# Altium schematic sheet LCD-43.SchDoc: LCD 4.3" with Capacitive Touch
size A4; Date: 25-FEB-2015; Author: A.B; CompanyName: STMicroelectronics; Address1: 12, Rue Jules HOROWITZ; Address2: 38019 Grenoble; Address3: FRANCE; DocumentNumber: MB1191; Revision: B-02; SheetNumber: 14; SheetTotal: 14; Project: STM32F746G-DISCO
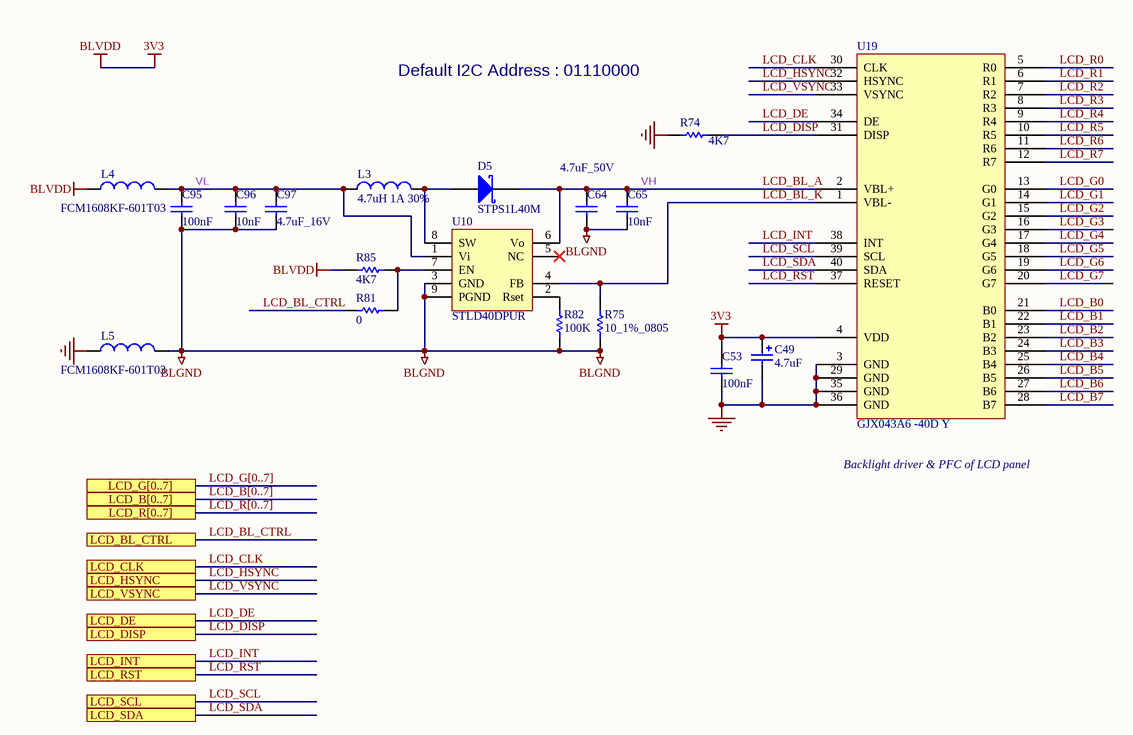
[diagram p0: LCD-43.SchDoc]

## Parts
C49  4.7uF  [TAN-A]
C53  100nF  [0402C]
C64  4.7uF_50V  [1206C]
C65  10nF  [0603C]
C95  100nF  [0603C]
C96  10nF  [0603C]
C97  4.7uF_16V  [1206C]
D5  STPS1L40M  [DO216-AA]
L3  4.7uH 1A 30%  [1210L]
L4  FCM1608KF-601T03  [0603L]
L5  FCM1608KF-601T03  [0603L]
R74  4K7  [0402R]
R75  10_1%_0805  [0805R]
R81  0  [0402R]
R82  100K  [0402R]
R85  4K7  [0402R]
U10  STLD40DPUR  [QFN8_0R65_3X3_ST]
U19  GJX043A6 -40D Y  [LCD_Kunjian_ HT043C_40P_P080_FLEX_FOLDED]

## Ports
LCD_B[0..7], LCD_BL_CTRL, LCD_CLK, LCD_DE, LCD_DISP, LCD_G[0..7], LCD_HSYNC, LCD_INT, LCD_R[0..7], LCD_RST, LCD_SCL, LCD_SDA, LCD_VSYNC

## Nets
3V3: C49.1 C53.2 L4.1 R85.2 U19.4(VDD)  [also labelled BLVDD]
BLGND: C64.2 C65.1 C95.1 C96.1 C97.2 L5.2 R75.1 R82.2 U10.3(GND) U10.9(PGND)
GND: C49.2 C53.1 L5.1 R74.2 U19.3(GND) U19.29(GND) U19.35(GND) U19.36(GND)
LCD_B0: U19.21(B0)
LCD_B1: U19.22(B1)
LCD_B2: U19.23(B2)
LCD_B3: U19.24(B3)
LCD_B4: U19.25(B4)
LCD_B5: U19.26(B5)
LCD_B6: U19.27(B6)
LCD_B7: U19.28(B7)
LCD_BL_A: C64.1 C65.2 D5.2(K) U10.6(Vo) U19.2(VBL+)  [also labelled VH]
LCD_BL_CTRL: R81.2 ; port LCD_BL_CTRL
LCD_BL_K: R75.2 U10.4(FB) U19.1(VBL-)
LCD_CLK: U19.30(CLK) ; port LCD_CLK
LCD_DE: U19.34(DE) ; port LCD_DE
LCD_DISP: R74.1 U19.31(DISP) ; port LCD_DISP
LCD_G0: U19.13(G0)
LCD_G1: U19.14(G1)
LCD_G2: U19.15(G2)
LCD_G3: U19.16(G3)
LCD_G4: U19.17(G4)
LCD_G5: U19.18(G5)
LCD_G6: U19.19(G6)
LCD_G7: U19.20(G7)
LCD_HSYNC: U19.32(HSYNC) ; port LCD_HSYNC
LCD_INT: U19.38(INT) ; port LCD_INT
LCD_R0: U19.5(R0)
LCD_R1: U19.6(R1)
LCD_R2: U19.7(R2)
LCD_R3: U19.8(R3)
LCD_R4: U19.9(R4)
LCD_R5: U19.10(R5)
LCD_R6: U19.11(R6)
LCD_R7: U19.12(R7)
LCD_RST: U19.37(RESET) ; port LCD_RST
LCD_SCL: U19.39(SCL) ; port LCD_SCL
LCD_SDA: U19.40(SDA) ; port LCD_SDA
LCD_VSYNC: U19.33(VSYNC) ; port LCD_VSYNC
VL: C95.2 C96.2 C97.1 L3.1 L4.2 U10.1(Vi)
NetD5_1: D5.1(A) L3.2 U10.8(SW)
NetR81_1: R81.1 R85.1 U10.7(EN)
NetR82_1: R82.1 U10.2(Rset)

Not connected (* = marked no-connect by the designer): U10 5(NC)*

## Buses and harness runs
bus LCD_B[0..7] = port LCD_B[0..7]
bus LCD_G[0..7] = port LCD_G[0..7]
bus LCD_R[0..7] = port LCD_R[0..7]

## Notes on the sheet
- Default I2C Address : 01110000
- Backlight driver & PFC of LCD panel

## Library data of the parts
C49 = Cap_4.7uF_POL_10%_TANA: Polarized Capacitor,4.7uF,16V,10%,typeA,AVX; Manuf_Part_1: TAJA475K016R
C53 = Cap_100nF_X7R_10%_0402: Capacitor,100nF,16V,X7R,10%,0402,YAGEO; Manuf_Part_1: CC0402KRX7R7BB104
C64 = Cap_4.7uF_X7R_10%_1206: Capacitor,4.7uF,50V, X7R,10%,1206,AVX; Manuf_Part_1: 12065C475KAT2A
C65 C96 = Cap_10nF_X7R_10%_0603: Capacitor,10nF,50V,X7R,10%,0603,YAGEO; Manuf_Part_1: CC0603KRX7R9BB103
C95 = Cap_100nF_X7R_10%_0603: Capacitor,100nF,16V,X7R,10%,0603,YAGEO; Manuf_Part_1: CC0603KRX7R9BB104
C97 = Cap_4.7uF_X5R_10%_1206: Capacitor,4.7uF,16V, X5R,10%,1206,AVX; Manuf_Part_1: 1206YD475KAT2A
D5 = STPS1L40M: Low Drop power Schottky rectifier(1A, 40V, 0.4V); Manuf_1: STM; Provided: ST; Ref St: 9151085; ECCN_US/EU: EAR99/NEC
L3 = Ind_4.7uH_1A_30%: FIXED IND 4.7UH 1A 180 MOHM 30% SMD; Manuf_Part_1: LQH32PN4R7NN0L; Manuf_1: MURATA; Order: 490-5338-1-ND
L4 L5 = BEAD_600R_350MA_0603: Bead,600R,350mA,0603,FCM1608KF-601T03,Tai-tech; Manuf_2: TDK; Manuf_Part_2: MPZ1608S300A; Manuf_Part_3: BLM18PG121SN1D; Manuf_3: MURATA; Value: 100uH; Description_2: Bead,30R,5A,0603,MPZ1608S300A,TDK; Description_3: Bead,120R,2A,0603,BLM18PG121SN1D,MURATA
R74 R85 = Res_4K7_1%_0402: Resistor,4K7,0402,1%,YAGEO; Manuf_Part_1: RT0402FRE074K7L
R75 = Res_10_1%_0805: Resistor,10,0805,1%,Stackpole,1/4W; Manuf_Part_1: RNCP0805FTD10R0; Manuf_1: Stackpole Electronics Inc; Value: 10
R81 = Res_0_5%_0402: Resistor,0,0402,5%,YAGEO; Manuf_Part_1: RC0402JR-070RL; Order: 2363467
R82 = Res_100K_1%_0402: Resistor,100K,0402,1%,YAGEO; Manuf_Part_1: RT0402FRE07100KL
U10 = STLD40DPUR: White LED power supply for large display backlight, QFN8; Manuf_1: STM; ECCN_US/EU: EAR99/NEC; Ref St: xxxxxxxxx; Provided: ST
U19 = HT043C: 4.3 inch TFT 480*272 pixels with LED Backlight and Capacitive touch panel, high luminance; Manuf_1: Shenzhen GJX Electronics Technology Co.,Ltd; ECCN_US/EU: EAR99/NEC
